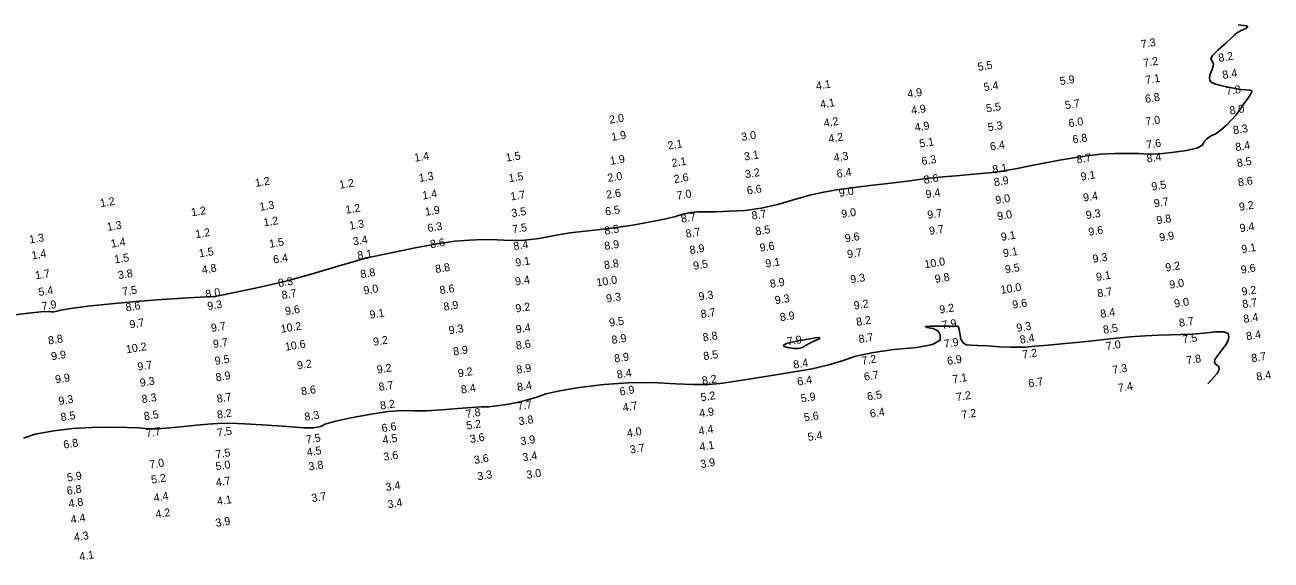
# Model space of a CAD drawing. Extents: x 988130 to 1132882, y 654656 to 841453.
# Drawn here: x 1108617 to 1109396, y 666656 to 666990 of the extents above; entities that cross this region are included whole.
import ezdxf

# ---------------------------------------------------------------- set-up
doc = ezdxf.new("R2010")
doc.units = 0
doc.layers.add('V-TOPO-MAJR', color=7, linetype='Continuous')
doc.layers.add('V-TOPO-SOUN', color=7, linetype='Continuous')

msp = doc.modelspace()

# ---------------------------------------------------------------- linework, layer by layer
at = {"layer": 'V-TOPO-MAJR'}
for points in [[(1109375.05, 666990.22), (1109380.25, 666989.66), (1109380.98, 666989.03), (1109379.84, 666988.04), (1109376.83, 666986.7), (1109374.63, 666985.56), (1109373.26, 666984.61), (1109372.7, 666983.85), (1109370.69, 666981.92), (1109367.23, 666978.8), (1109362.33, 666974.51), (1109359.22, 666971.33), (1109357.9, 666969.27), (1109358.39, 666968.33), (1109358.82, 666967.46), (1109359.21, 666966.68), (1109359.56, 666965.97), (1109359.38, 666964.51), (1109358.68, 666962.31), (1109357.46, 666959.37), (1109356.97, 666957.08), (1109357.21, 666955.45), (1109358.19, 666954.48), (1109360.43, 666953.46), (1109363.95, 666952.39), (1109368.73, 666951.26), (1109373.01, 666950.45), (1109376.79, 666949.95), (1109380.06, 666949.75), (1109382.27, 666949.42), (1109383.43, 666948.94), (1109383.53, 666948.32), (1109382.76, 666946.77), (1109381.11, 666944.3), (1109378.59, 666940.91), (1109376.78, 666938.42), (1109375.67, 666936.82), (1109375.27, 666936.13), (1109374.96, 666935.61), (1109374.76, 666935.28), (1109374.65, 666935.11), (1109373.48, 666933.82), (1109371.24, 666931.39), (1109367.93, 666927.82), (1109364.58, 666924.84), (1109361.18, 666922.44), (1109357.73, 666920.62), (1109355.17, 666918.78), (1109353.48, 666916.9), (1109352.68, 666915), (1109349.1, 666913.29), (1109342.74, 666911.78), (1109333.61, 666910.46), (1109325.59, 666909.7), (1109318.71, 666909.5), (1109312.94, 666909.85), (1109306.06, 666909.94), (1109298.06, 666909.79), (1109288.94, 666909.38), (1109277.39, 666908.04), (1109263.41, 666905.77), (1109247.01, 666902.56), (1109235.73, 666900.38), (1109229.57, 666899.2), (1109228.53, 666899.05), (1109227.63, 666898.9), (1109226.87, 666898.75), (1109226.24, 666898.6), (1109221.3, 666898.09), (1109212.06, 666897.23), (1109198.5, 666896.02), (1109187.89, 666894.99), (1109180.25, 666894.16), (1109175.56, 666893.53), (1109168.1, 666892.61), (1109157.85, 666891.41), (1109144.83, 666889.92), (1109133.51, 666888.48), (1109123.91, 666887.08), (1109116.02, 666885.73), (1109107.27, 666883.76), (1109097.66, 666881.16), (1109087.19, 666877.94), (1109076.91, 666875.64), (1109066.81, 666874.26), (1109056.91, 666873.81), (1109048.7, 666873.51), (1109042.18, 666873.37), (1109037.35, 666873.38), (1109032.58, 666872.9), (1109027.87, 666871.94), (1109023.23, 666870.48), (1109016.48, 666868.86), (1109007.63, 666867.07), (1108996.68, 666865.13), (1108986.23, 666863.54), (1108976.28, 666862.3), (1108966.83, 666861.42), (1108957.32, 666860.21), (1108947.76, 666858.68), (1108938.13, 666856.81), (1108928.95, 666855.74), (1108920.21, 666855.48), (1108911.91, 666856.02), (1108903.35, 666856.13), (1108894.53, 666855.79), (1108885.46, 666855.02), (1108874.47, 666853.48), (1108861.58, 666851.17), (1108846.77, 666848.09), (1108836.75, 666846), (1108831.53, 666844.88), (1108831.1, 666844.75), (1108830.64, 666844.64), (1108830.14, 666844.56), (1108829.61, 666844.5), (1108823.93, 666842.87), (1108813.11, 666839.65), (1108797.14, 666834.84), (1108781.56, 666830.61), (1108766.37, 666826.93), (1108751.58, 666823.82), (1108741.69, 666821.74), (1108736.69, 666820.69), (1108736.6, 666820.66), (1108736.42, 666820.63), (1108736.16, 666820.62), (1108735.82, 666820.61), (1108730.01, 666820.28), (1108718.75, 666819.61), (1108702.03, 666818.62), (1108686, 666817.42), (1108670.67, 666816.02), (1108656.04, 666814.42), (1108645.51, 666813.1), (1108639.08, 666812.06), (1108636.76, 666811.29), (1108634.81, 666810.89), (1108633.22, 666810.87), (1108631.99, 666811.22), (1108626.65, 666810.88), (1108617.19, 666809.85), (1108603.62, 666808.13)], [(1108615.75, 666731.97), (1108623.11, 666734.5), (1108634.72, 666736.54), (1108646.52, 666737.93), (1108658.5, 666738.68), (1108670.67, 666738.78), (1108680.54, 666738.69), (1108688.11, 666738.4), (1108693.38, 666737.91), (1108699.81, 666737.91), (1108707.4, 666738.38), (1108716.15, 666739.32), (1108724.06, 666740.11), (1108731.13, 666740.74), (1108737.35, 666741.21), (1108745.05, 666741.3), (1108754.24, 666741.01), (1108764.9, 666740.35), (1108774.56, 666739.69), (1108783.24, 666739.05), (1108790.92, 666738.41), (1108797.07, 666738.5), (1108801.69, 666739.32), (1108804.78, 666740.87), (1108811.04, 666742.67), (1108820.45, 666744.74), (1108833.03, 666747.07), (1108843.76, 666748.55), (1108852.62, 666749.18), (1108859.63, 666748.96), (1108867.77, 666749.09), (1108877.05, 666749.59), (1108887.47, 666750.45), (1108895.86, 666751.08), (1108902.23, 666751.48), (1108906.57, 666751.64), (1108911.72, 666752.18), (1108917.66, 666753.08), (1108924.4, 666754.36), (1108930.75, 666755.89), (1108936.71, 666757.65), (1108942.29, 666759.65), (1108951.12, 666761.62), (1108963.21, 666763.57), (1108978.56, 666765.48), (1108993.73, 666766.53), (1109008.73, 666766.7), (1109023.56, 666766), (1109034.35, 666765.57), (1109041.11, 666765.42), (1109043.84, 666765.54), (1109046.42, 666765.7), (1109048.86, 666765.88), (1109051.14, 666766.11), (1109058.31, 666767.15), (1109070.36, 666769.02), (1109087.29, 666771.72), (1109100.05, 666773.82), (1109108.64, 666775.34), (1109113.06, 666776.26), (1109119.11, 666777.87), (1109126.78, 666780.16), (1109136.08, 666783.14), (1109147.11, 666785.54), (1109159.86, 666787.37), (1109174.34, 666788.63), (1109183.99, 666790.58), (1109188.81, 666793.22), (1109188.8, 666796.54), (1109187.35, 666798.99), (1109184.46, 666800.55), (1109180.12, 666801.24), (1109179.51, 666801.71), (1109182.64, 666801.97), (1109189.49, 666802.02), (1109194.42, 666802.06), (1109197.43, 666802.07), (1109198.52, 666802.07), (1109199.35, 666801.95), (1109199.9, 666801.72), (1109200.2, 666801.37), (1109200.59, 666799.95), (1109201.09, 666797.47), (1109201.69, 666793.92), (1109203.01, 666791.53), (1109205.05, 666790.28), (1109207.81, 666790.19), (1109212.25, 666789.97), (1109218.35, 666789.63), (1109226.12, 666789.16), (1109232.61, 666788.89), (1109237.84, 666788.82), (1109241.79, 666788.95), (1109247.93, 666789.37), (1109256.26, 666790.08), (1109266.78, 666791.08), (1109276.09, 666792.02), (1109284.21, 666792.91), (1109291.12, 666793.74), (1109298.86, 666794.52), (1109307.42, 666795.24), (1109316.81, 666795.9), (1109325.26, 666796.36), (1109332.78, 666796.62), (1109339.37, 666796.67), (1109346.25, 666797), (1109353.42, 666797.59), (1109360.89, 666798.46), (1109366, 666798.37), (1109368.75, 666797.32), (1109369.15, 666795.31), (1109368.66, 666793), (1109367.28, 666790.38), (1109365.02, 666787.46), (1109363.11, 666784.94), (1109361.55, 666782.83), (1109360.35, 666781.13), (1109360.17, 666779.56), (1109361.03, 666778.12), (1109362.92, 666776.8), (1109363.2, 666774.86), (1109361.89, 666772.29), (1109356.05, 666765.9)]]:
    msp.add_lwpolyline(points, dxfattribs=at)
msp.add_lwpolyline([(1109092.76, 666791.24), (1109097.08, 666792.24), (1109100.44, 666792.9), (1109105, 666793.71), (1109110.75, 666794.67), (1109113.47, 666794.81), (1109113.14, 666794.13), (1109109.78, 666792.63), (1109106.9, 666791.22), (1109104.52, 666789.9), (1109102.63, 666788.66), (1109100.14, 666788.03), (1109097.05, 666787.99), (1109093.36, 666788.56), (1109091.24, 666789.17), (1109090.7, 666789.83)], close=True, dxfattribs=at)

# ---------------------------------------------------------------- texts
at = {"layer": 'V-TOPO-SOUN'}
for s, p in [('7.3', (1109314.6, 666975.65)), ('5.5', (1109212.51, 666961.5)), ('7.2', (1109316.07, 666963.91)), ('8.2', (1109363.02, 666967.09)), ('8.4', (1109365.53, 666956.45)), ('4.1', (1109111.5, 666949.62)), ('5.4', (1109216.3, 666948.82)), ('5.9', (1109263.89, 666952.56)), ('7.1', (1109317.34, 666953.32)), ('7.8', (1109367.76, 666946.3)), ('4.1', (1109114.05, 666938.08)), ('4.9', (1109168.64, 666944.53)), ('6.8', (1109317.16, 666941.46)), ('4.9', (1109170.92, 666934.25)), ('5.5', (1109217.84, 666935.5)), ('5.7', (1109267.13, 666937.53)), ('8.0', (1109369.95, 666934.17)), ('2.0', (1108982.26, 666928.48)), ('4.2', (1109116.34, 666926.37)), ('4.9', (1109173.15, 666923.64)), ('5.3', (1109218.89, 666923.76)), ('6.0', (1109269.3, 666926.25)), ('7.0', (1109317.38, 666927.26)), ('1.9', (1108983.61, 666917.71)), ('3.0', (1109064.85, 666917.69)), ('4.2', (1109119.25, 666916.59)), ('6.8', (1109271.8, 666916.08)), ('8.3', (1109372.2, 666921.86)), ('2.1', (1109018.84, 666912.31)), ('5.1', (1109176.07, 666913.56)), ('6.4', (1109220.27, 666911.69)), ('7.6', (1109317.95, 666912.78)), ('8.4', (1109373.58, 666911.35)), ('1.4', (1108860.46, 666904.7)), ('1.5', (1108917.65, 666904.78)), ('1.9', (1108982.8, 666902.76)), ('2.1', (1109021.27, 666901.4)), ('3.1', (1109066.58, 666905.42)), ('4.3', (1109122.53, 666904.73)), ('6.3', (1109177.42, 666902.58)), ('8.7', (1109274.31, 666903.64)), ('8.4', (1109318.12, 666904.12)), ('8.5', (1109374.54, 666901.38)), ('1.3', (1108863.27, 666892.06)), ('1.5', (1108919.39, 666891.93)), ('2.0', (1108981.21, 666892.08)), ('2.6', (1109022.64, 666891.32)), ('3.2', (1109067.18, 666894.38)), ('6.4', (1109124.48, 666894.62)), ('8.6', (1109178.82, 666890.89)), ('8.1', (1109221.78, 666897.3)), ('9.1', (1109276.93, 666892.92)), ('1.2', (1108760.92, 666889)), ('1.2', (1108813.56, 666887.81)), ('6.6', (1109068.33, 666884.18)), ('8.9', (1109222.67, 666889.44)), ('9.5', (1109321.12, 666886.71)), ('8.6', (1109375.23, 666889.2)), ('1.2', (1108664.06, 666876.35)), ('1.4', (1108865.45, 666881.13)), ('1.7', (1108920.56, 666880.5)), ('2.6', (1108980.34, 666881.58)), ('7.0', (1109024.46, 666881.05)), ('9.0', (1109125.83, 666882.74)), ('9.4', (1109180.04, 666881.86)), ('9.0', (1109223.62, 666878.23)), ('9.4', (1109278.45, 666879.78)), ('9.7', (1109322.66, 666876.23)), ('1.2', (1108721.01, 666870.59)), ('1.3', (1108763.73, 666874.04)), ('1.2', (1108817.47, 666872.18)), ('1.9', (1108867.16, 666870.91)), ('3.5', (1108921.15, 666870.04)), ('6.5', (1108979.73, 666871.11)), ('8.7', (1109071.27, 666868.53)), ('9.0', (1109127.33, 666869.55)), ('9.7', (1109181.1, 666868.97)), ('9.0', (1109224.79, 666868.15)), ('9.3', (1109280.16, 666868.83)), ('9.2', (1109375.89, 666873.99)), ('1.3', (1108668.35, 666861.46)), ('1.2', (1108766.2, 666864.29)), ('1.3', (1108819.79, 666862.28)), ('6.3', (1108868.67, 666860.74)), ('7.5', (1108921.68, 666859.99)), ('8.7', (1109027.12, 666866.58)), ('9.8', (1109324.26, 666865.64)), ('9.4', (1109376.28, 666860.68)), ('1.3', (1108619.76, 666853.6)), ('1.2', (1108723.65, 666856.93)), ('3.4', (1108822.09, 666852.41)), ('8.5', (1108979.2, 666859.09)), ('8.7', (1109030.03, 666857.24)), ('8.5', (1109073.67, 666858.72)), ('9.6', (1109129.52, 666854.33)), ('9.7', (1109182.18, 666858.97)), ('9.1', (1109227.08, 666855.23)), ('9.6', (1109281.75, 666858.42)), ('9.9', (1109326.06, 666854.91)), ('1.4', (1108670.79, 666851)), ('1.5', (1108725.83, 666844.94)), ('1.5', (1108769.73, 666850.91)), ('8.6', (1108870.35, 666850.68)), ('8.4', (1108922.45, 666849.47)), ('8.9', (1108979.25, 666849.55)), ('8.9', (1109032.58, 666847.03)), ('9.6', (1109076.31, 666848.49)), ('9.7', (1109130.99, 666844.41)), ('9.1', (1109228.4, 666845.06)), ('9.1', (1109377.35, 666847.55)), ('1.4', (1108621.23, 666843.69)), ('1.5', (1108673.01, 666841.16)), ('6.4', (1108772.28, 666841.05)), ('8.1', (1108824.94, 666843.61)), ('9.1', (1108923.62, 666839.14)), ('8.8', (1108979.01, 666837.59)), ('9.5', (1109034.75, 666837.2)), ('9.1', (1109079.86, 666838.58)), ('10.0 ', (1109179.28, 666838.12)), ('9.3', (1109284.38, 666841.49)), ('1.7', (1108623.5, 666831.22)), ('3.8', (1108675.27, 666831.31)), ('4.8', (1108727.61, 666834.73)), ('8.8', (1108826.83, 666831.94)), ('8.8', (1108873.53, 666835.16)), ('9.3', (1109132.99, 666828.65)), ('9.8', (1109185.76, 666828.95)), ('9.5', (1109229.61, 666834.91)), ('9.1', (1109286.54, 666830.21)), ('9.2', (1109329.85, 666836.1)), ('9.6', (1109377.01, 666834.72)), ('7.5', (1108677.93, 666820.98)), ('8.3', (1108775.34, 666826.41)), ('9.0', (1108828.73, 666821.78)), ('8.6', (1108876.3, 666821.9)), ('9.4', (1108923.44, 666827.35)), ('10.0 ', (1108974.32, 666826.7)), ('8.9', (1109082.71, 666825.89)), ('10.0 ', (1109226.88, 666822.1)), ('9.0', (1109332.31, 666825.36)), ('9.2', (1109377.49, 666821.02)), ('5.4', (1108625.52, 666820.76)), ('8.0', (1108729.94, 666819.54)), ('8.7', (1108777.56, 666818.9)), ('9.3', (1108980.37, 666816.72)), ('9.3', (1109038.14, 666817.95)), ('9.3', (1109085.82, 666815.65)), ('8.7', (1109287.38, 666819.93)), ('9.0', (1109335.37, 666813.57)), ('8.7', (1109377.95, 666813.16)), ('7.9', (1108627.62, 666811.92)), ('8.6', (1108680.05, 666811.15)), ('9.3', (1108731.11, 666811.99)), ('9.6', (1108779.71, 666808.86)), ('9.1', (1108832.53, 666806.62)), ('8.9', (1108878.74, 666811.61)), ('9.2', (1108923.69, 666810.48)), ('8.7', (1109039.5, 666806.99)), ('9.2', (1109135.15, 666812.35)), ('9.2', (1109188.57, 666809.8)), ('9.6', (1109234.2, 666812.85)), ('8.4', (1109289.2, 666807.11)), ('9.7', (1108682.49, 666800.58)), ('9.7', (1108733.41, 666798.3)), ('10.2 ', (1108777.02, 666797.79)), ('9.4', (1108923.94, 666797.48)), ('9.5', (1108982.26, 666801.58)), ('8.9', (1109088.95, 666805.04)), ('8.2', (1109136.62, 666802.1)), ('7.9', (1109190.11, 666800.16)), ('9.3', (1109236.8, 666798.36)), ('8.7', (1109338.38, 666801.47)), ('8.4', (1109378.64, 666803.95)), ('8.8', (1108631.6, 666790.47)), ('9.3', (1108881.98, 666796.88)), ('8.9', (1108983.78, 666790.85)), ('8.8', (1109040.76, 666792.38)), ('7.9', (1109093.4, 666789.9)), ('8.7', (1109138.14, 666791.38)), ('8.4', (1109238.86, 666791.01)), ('8.5', (1109290.95, 666797.22)), ('7.5', (1109340.53, 666791.08)), ('8.4', (1109380.35, 666793.21)), ('10.2 ', (1108680.26, 666785)), ('9.7', (1108734.67, 666788.25)), ('10.6 ', (1108779.62, 666786.59)), ('9.2', (1108834.74, 666789.64)), ('8.9', (1108884.75, 666783.58)), ('8.6', (1108923.99, 666787.29)), ('7.9', (1109191.43, 666788.38)), ('7.0', (1109292.72, 666786.96)), ('9.9', (1108633.55, 666780.61)), ('9.7', (1108687.42, 666774.17)), ('9.5', (1108735.74, 666777.73)), ('9.2', (1108787.22, 666774.85)), ('8.9', (1108985.42, 666779.21)), ('8.5', (1109041.13, 666780.67)), ('8.4', (1109097.38, 666775.4)), ('7.2', (1109140, 666777.82)), ('6.9', (1109193.44, 666777.69)), ('7.2', (1109240.46, 666781.72)), ('7.8', (1109342.92, 666778.09)), ('8.7', (1109383.58, 666779.46)), ('8.9', (1108736.37, 666767.5)), ('9.2', (1108837.08, 666772.29)), ('9.2', (1108887.7, 666770)), ('8.9', (1108924.31, 666772.24)), ('8.4', (1108987.06, 666769.16)), ('6.7', (1109141.48, 666767.87)), ('7.3', (1109296.76, 666772.11)), ('8.4', (1109386.73, 666767.89)), ('9.9', (1108636.01, 666766.16)), ('9.3', (1108688.94, 666764.05)), ('8.6', (1108789.7, 666758.7)), ('8.7', (1108838.2, 666761.5)), ('8.4', (1108889.62, 666759.81)), ('8.4', (1108924.7, 666761.38)), ('6.9', (1108988.83, 666758.57)), ('8.2', (1109040.25, 666765.38)), ('6.4', (1109099.79, 666764.82)), ('7.1', (1109196.79, 666766.28)), ('6.7', (1109244.24, 666763.71)), ('7.4', (1109300.26, 666760.89)), ('9.3', (1108638.11, 666752.7)), ('8.3', (1108690.14, 666753.81)), ('8.7', (1108736.97, 666754.12)), ('5.2', (1109039.39, 666754.97)), ('5.9', (1109102.01, 666754.29)), ('6.5', (1109143.44, 666755.51)), ('7.2', (1109199.09, 666755.14)), ('8.5', (1108691.45, 666743.17)), ('8.2', (1108737.19, 666744.1)), ('8.2', (1108839.13, 666749.79)), ('7.8', (1108892.65, 666744.55)), ('7.7', (1108924.8, 666749.27)), ('4.7', (1108990.69, 666748.64)), ('4.9', (1109038.53, 666744.92)), ('6.4', (1109145.22, 666744.76)), ('7.2', (1109202.43, 666744.03)), ('8.5', (1108639.45, 666742.52)), ('8.3', (1108791.82, 666742.82)), ('6.6', (1108840.07, 666735.7)), ('5.2', (1108892.94, 666737.33)), ('3.8', (1108925.67, 666740.02)), ('5.6', (1109103.95, 666742.39)), ('7.7', (1108692.74, 666732.58)), ('7.5', (1108737.2, 666732.82)), ('7.5', (1108792.74, 666728.57)), ('4.5', (1108840.64, 666728.39)), ('3.6', (1108895.17, 666728.94)), ('3.9', (1108926.77, 666727.55)), ('4.0', (1108993.32, 666732.58)), ('4.4', (1109038.12, 666733.98)), ('5.4', (1109106.31, 666730.17)), ('6.8', (1108641.16, 666725.42)), ('4.5', (1108793.23, 666720.63)), ('3.7', (1108995.23, 666722.36)), ('4.1', (1109038.74, 666724.03)), ('7.0', (1108694.91, 666712.94)), ('7.5', (1108736.25, 666719.3)), ('5.0', (1108736.29, 666711.83)), ('3.6', (1108841.2, 666717.82)), ('3.6', (1108897.74, 666715.84)), ('3.4', (1108928.07, 666717.44)), ('3.9', (1109039.24, 666713.22)), ('5.9', (1108643.42, 666704.83)), ('3.8', (1108794.42, 666711.69)), ('3.3', (1108899.85, 666705.63)), ('3.0', (1108930.53, 666706.55)), ('6.8', (1108643.28, 666696.59)), ('5.2', (1108696.02, 666703.51)), ('4.7', (1108736.43, 666701.77)), ('3.4', (1108842.51, 666698.91)), ('4.8', (1108644.38, 666688.54)), ('4.4', (1108697.56, 666692.2)), ('4.1', (1108737.17, 666690.01)), ('3.7', (1108796.23, 666692.02)), ('4.2', (1108698.71, 666681.92)), ('3.4', (1108843.77, 666688.1)), ('4.4', (1108645.7, 666678.61)), ('3.9', (1108736.23, 666676.53)), ('4.3', (1108647.74, 666667.51)), ('4.1', (1108651.07, 666655.44))]:
    msp.add_text(s, height=5, rotation=9.0039, dxfattribs=at).set_placement(p)

doc.saveas('drawing.dxf')
